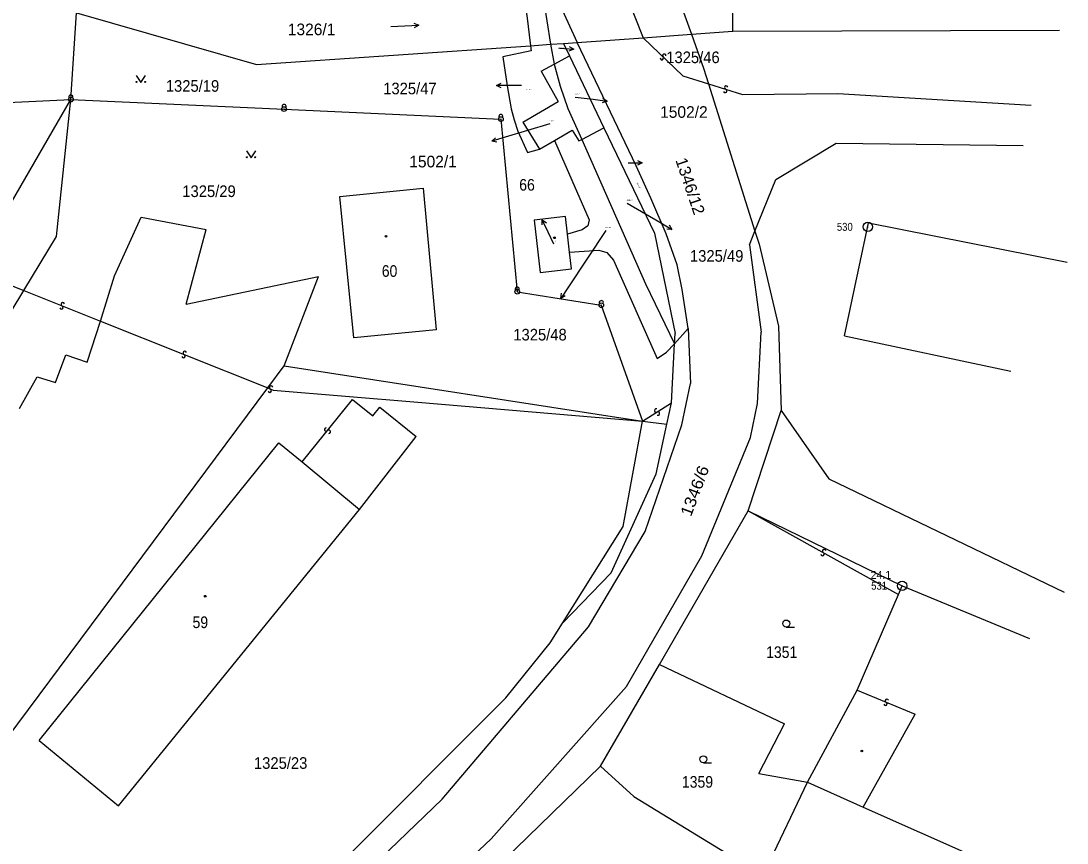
# Model space of a CAD drawing. Extents: x -871901 to -870967, y -1075952 to -1074892.
# Drawn here: x -871136.9 to -871047, y -1075290 to -1075219.4 of the extents above; entities that cross this region are included whole.
import ezdxf
from ezdxf.enums import TextEntityAlignment as Align

# ---------------------------------------------------------------- set-up
doc = ezdxf.new("R2010")
doc.units = 0
doc.header["$LTSCALE"] = 0.4
for name, color, linetype, lineweight in [('1', 7, 'Continuous', 25), ('16', 7, 'Continuous', 25), ('24', 7, 'Continuous', 25), ('25', 7, 'Continuous', 25), ('4', 7, 'Continuous', 25)]:
    doc.layers.add(name, color=color, linetype=linetype, lineweight=lineweight)
for name, color, linetype in [('17', 7, 'Continuous'), ('18', 7, 'Continuous'), ('19', 7, 'Continuous')]:
    doc.layers.add(name, color=color, linetype=linetype)

msp = doc.modelspace()

# ---------------------------------------------------------------- linework, layer by layer
at = {"layer": '1'}
for p, q in [((-871132.14, -1075218.66), (-871116.67, -1075223.11)), ((-871083.4, -1075220.8), (-871079.27, -1075220.49)), ((-871075.69, -1075220.23), (-871047.62, -1075220.14)), ((-871090.25, -1075221.28), (-871089.08, -1075221.2)), ((-871090.25, -1075221.28), (-871089.74, -1075222.36)), ((-871089.08, -1075221.2), (-871083.4, -1075220.8)), ((-871089.74, -1075222.36), (-871086.79, -1075228.53)), ((-871092.19, -1075223.66), (-871090.73, -1075226.28)), ((-871149.91, -1075255.96), (-871132.62, -1075226.11)), ((-871133.87, -1075237.87), (-871132.62, -1075226.11)), ((-871132.62, -1075226.11), (-871114.29, -1075226.93)), ((-871114.29, -1075226.93), (-871095.65, -1075227.79)), ((-871093.75, -1075228.06), (-871090.73, -1075226.28)), ((-871095.65, -1075227.79), (-871094.24, -1075242.63)), ((-871093.75, -1075228.06), (-871092.33, -1075230.38)), ((-871089.52, -1075228.73), (-871088.95, -1075229.67)), ((-871072.01, -1075232.97), (-871066.83, -1075229.86)), ((-871066.83, -1075229.86), (-871050.73, -1075230.05)), ((-871073.8, -1075237.43), (-871072.01, -1075232.97)), ((-871126.58, -1075236.21), (-871120.98, -1075237.29)), ((-871066.09, -1075246.41), (-871064.05, -1075236.72)), ((-871064.05, -1075236.72), (-871046.96, -1075240.09)), ((-871122.72, -1075243.71), (-871120.98, -1075237.29)), ((-871136.68, -1075242.53), (-871133.87, -1075237.87)), ((-871122.72, -1075243.71), (-871111.33, -1075241.33)), ((-871141.5, -1075250.52), (-871136.68, -1075242.53)), ((-871094.24, -1075242.63), (-871087.01, -1075243.79)), ((-871087.01, -1075243.79), (-871083.47, -1075253.75)), ((-871066.09, -1075246.41), (-871051.8, -1075249.47)), ((-871133.96, -1075250.43), (-871133.07, -1075248.06)), ((-871133.07, -1075248.06), (-871131.22, -1075248.69)), ((-871114.29, -1075249), (-871083.47, -1075253.75)), ((-871137.04, -1075252.66), (-871135.52, -1075249.95)), ((-871135.52, -1075249.95), (-871133.96, -1075250.43)), ((-871156.43, -1075305.59), (-871115.7, -1075250.9)), ((-871081.37, -1075254), (-871080.98, -1075252.18)), ((-871074.38, -1075261.46), (-871071.55, -1075252.85)), ((-871083.47, -1075253.75), (-871081.37, -1075254)), ((-871082.28, -1075258.28), (-871081.37, -1075254)), ((-871135.35, -1075281.2), (-871114.73, -1075255.63)), ((-871114.73, -1075255.63), (-871112.73, -1075257.25)), ((-871112.73, -1075257.25), (-871107.81, -1075261.35)), ((-871086.17, -1075266.8), (-871082.28, -1075258.28)), ((-871067.46, -1075258.72), (-871047.21, -1075268.46)), ((-871128.52, -1075286.81), (-871107.81, -1075261.35)), ((-871082.01, -1075274.66), (-871074.38, -1075261.46)), ((-871074.38, -1075261.46), (-871061.14, -1075267.9)), ((-871090.35, -1075271.13), (-871086.17, -1075266.8)), ((-871065.01, -1075276.88), (-871061.46, -1075268.64)), ((-871091.41, -1075272.82), (-871090.35, -1075271.13)), ((-871095.22, -1075277.55), (-871091.41, -1075272.82)), ((-871087.07, -1075283.41), (-871082.01, -1075274.66)), ((-871082.01, -1075274.66), (-871071.25, -1075279.76)), ((-871069.29, -1075284.78), (-871065.01, -1075276.88)), ((-871109.75, -1075292.07), (-871095.22, -1075277.55)), ((-871073.47, -1075284.05), (-871071.25, -1075279.76)), ((-871135.35, -1075281.2), (-871128.52, -1075286.81)), ((-871095.43, -1075291.53), (-871087.07, -1075283.41)), ((-871087.07, -1075283.41), (-871084.21, -1075286.02)), ((-871073.47, -1075284.05), (-871069.29, -1075284.78)), ((-871073.1, -1075292.79), (-871069.29, -1075284.78)), ((-871069.29, -1075284.78), (-871064.49, -1075286.92)), ((-871084.21, -1075286.02), (-871073.1, -1075292.79)), ((-871064.49, -1075286.92), (-871054.81, -1075291.23))]:
    msp.add_line(p, q, dxfattribs=at)
for points in [[(-871132.62, -1075226.11), (-871132.14, -1075218.66), (-871123.91, -1075214.69)], [(-871079.27, -1075220.49), (-871075.69, -1075220.23), (-871075.68, -1075215.86)], [(-871079.27, -1075220.49), (-871078.22, -1075223.41), (-871077.79, -1075224.77), (-871073.8, -1075237.43)], [(-871116.67, -1075223.11), (-871093.1, -1075221.48), (-871091.39, -1075221.36), (-871090.25, -1075221.28)], [(-871093.1, -1075221.48), (-871093.05, -1075221.91), (-871095.49, -1075222.43), (-871095.12, -1075224.94), (-871094.75, -1075226.9), (-871094.5, -1075227.84), (-871094.19, -1075228.83), (-871093.36, -1075230.65), (-871092.33, -1075230.38)], [(-871091.39, -1075221.36), (-871091.06, -1075223.06), (-871090.54, -1075224.97), (-871089.88, -1075226.87), (-871088.7, -1075229.54), (-871083.2, -1075241.94), (-871080.72, -1075247.11)], [(-871089.74, -1075239.24), (-871087.22, -1075239.05), (-871086.55, -1075239.25), (-871085.96, -1075239.92), (-871082.22, -1075248.38), (-871081.4, -1075247.82), (-871080.72, -1075247.11), (-871079.54, -1075245.79), (-871080.05, -1075242.43), (-871080.49, -1075240.33), (-871081.43, -1075237.66), (-871082.74, -1075234.58), (-871084.01, -1075231.8), (-871089.08, -1075221.2)], [(-871092.19, -1075223.66), (-871091.06, -1075223.06), (-871089.74, -1075222.36)], [(-871142.34, -1075235.78), (-871141.97, -1075234.83), (-871140.11, -1075230.1), (-871138.66, -1075226.39), (-871132.62, -1075226.11)], [(-871092.33, -1075230.38), (-871091.05, -1075229.63), (-871089.52, -1075228.73)], [(-871088.95, -1075229.67), (-871088.7, -1075229.54), (-871086.79, -1075228.53)], [(-871086.79, -1075228.53), (-871082.45, -1075237.6), (-871080.67, -1075246.21)], [(-871091.05, -1075229.63), (-871088.06, -1075236.44), (-871088.18, -1075236.96), (-871088.65, -1075237.32), (-871089.92, -1075237.67), (-871090.09, -1075236.16), (-871092.79, -1075236.48), (-871092.27, -1075240.99), (-871089.57, -1075240.67), (-871089.74, -1075239.24), (-871089.92, -1075237.67)], [(-871131.22, -1075248.69), (-871130.08, -1075245.17), (-871128.88, -1075241.26), (-871126.58, -1075236.21)], [(-871073.8, -1075237.43), (-871073.45, -1075238.54), (-871071.78, -1075245.58)], [(-871115.7, -1075250.9), (-871114.29, -1075249), (-871111.33, -1075241.33)], [(-871071.78, -1075245.58), (-871071.55, -1075252.85), (-871067.46, -1075258.72)], [(-871080.98, -1075252.18), (-871080.72, -1075247.11), (-871080.67, -1075246.21)], [(-871061.46, -1075268.64), (-871061.14, -1075267.9), (-871050.19, -1075272.43)]]:
    msp.add_lwpolyline(points, dxfattribs=at)
msp.add_lwpolyline([(-871109.5, -1075234.44), (-871102.34, -1075233.74), (-871101.2, -1075245.89), (-871108.3, -1075246.6)], close=True, dxfattribs=at)
at = {"layer": '16'}
for p, q in [((-871090.62, -1075221.7), (-871090.58, -1075221.7)), ((-871090.58, -1075221.7), (-871089.381, -1075221.768)), ((-871094.83, -1075224.91), (-871096.03, -1075224.91)), ((-871093.88, -1075224.91), (-871094.83, -1075224.91)), ((-871089.26, -1075225.9), (-871087.7, -1075226.09)), ((-871087.7, -1075226.09), (-871086.509, -1075226.238)), ((-871091.45, -1075228.19), (-871095.29, -1075229.35)), ((-871095.29, -1075229.35), (-871096.438, -1075229.696)), ((-871084.69, -1075231.54), (-871083.49, -1075231.544)), ((-871084.78, -1075235.02), (-871081.97, -1075236.66)), ((-871091.57, -1075237.52), (-871092.086, -1075236.437)), ((-871081.97, -1075236.66), (-871080.936, -1075237.268)), ((-871091.09, -1075238.53), (-871091.57, -1075237.52)), ((-871086.61, -1075237.36), (-871089.83, -1075242.2)), ((-871089.83, -1075242.2), (-871090.495, -1075243.198))]:
    msp.add_line(p, q, dxfattribs=at)
for points in [[(-871089.769, -1075221.546), (-871089.381, -1075221.768), (-871089.793, -1075221.945)], [(-871095.63, -1075225.109), (-871096.03, -1075224.91), (-871095.63, -1075224.709)], [(-871086.881, -1075225.99), (-871086.509, -1075226.238), (-871086.931, -1075226.387)], [(-871095.998, -1075229.772), (-871096.438, -1075229.696), (-871096.113, -1075229.389)], [(-871083.889, -1075231.342), (-871083.49, -1075231.544), (-871083.89, -1075231.742)], [(-871092.094, -1075236.884), (-871092.086, -1075236.437), (-871091.733, -1075236.711)], [(-871081.179, -1075236.893), (-871080.936, -1075237.268), (-871081.382, -1075237.238)], [(-871090.107, -1075242.976), (-871090.495, -1075243.198), (-871090.44, -1075242.754)]]:
    msp.add_lwpolyline(points, dxfattribs=at)
at = {"layer": '24'}
for centre, radius in [((-871132.6195, -1075226.1095), 0.2005), ((-871132.6195, -1075226.1095), 0.00851), ((-871114.2895, -1075226.9295), 0.2005), ((-871114.2895, -1075226.9295), 0.00851), ((-871095.6495, -1075227.7895), 0.2005), ((-871095.6495, -1075227.7895), 0.00851), ((-871064.0895, -1075237.0495), 0.4005), ((-871064.0895, -1075237.0495), 0.0125), ((-871094.2395, -1075242.6295), 0.2005), ((-871094.2395, -1075242.6295), 0.00851), ((-871087.0095, -1075243.7895), 0.2005), ((-871087.0095, -1075243.7895), 0.00851), ((-871061.1395, -1075267.8995), 0.4005), ((-871061.1395, -1075267.8995), 0.0125)]:
    msp.add_circle(centre, radius, dxfattribs=at)
for centre in [(-871132.6198, -1075225.8836), (-871114.2898, -1075226.7036), (-871095.6498, -1075227.5636), (-871094.2398, -1075242.4036), (-871087.0098, -1075243.5636)]:
    msp.add_arc(centre, 0.1746, 328.19485, 209.95045, dxfattribs=at)
at = {"layer": '25'}
for p, q in [((-871105.108, -1075219.836), (-871102.711, -1075219.723)), ((-871071.11, -1075271.45), (-871070.409, -1075271.45)), ((-871078.23, -1075283.12), (-871077.529, -1075283.12))]:
    msp.add_line(p, q, dxfattribs=at)
for points in [[(-871103.12, -1075219.542), (-871102.711, -1075219.723), (-871103.101, -1075219.942)], [(-871127.01, -1075224.029), (-871126.61, -1075224.63), (-871126.209, -1075224.029)], [(-871117.53, -1075230.509), (-871117.13, -1075231.11), (-871116.729, -1075230.509)]]:
    msp.add_lwpolyline(points, dxfattribs=at)
for centre, radius in [((-871126.97, -1075224.59), 0.04), ((-871126.249, -1075224.59), 0.04), ((-871117.49, -1075231.07), 0.04), ((-871116.769, -1075231.07), 0.04), ((-871105.5295, -1075237.8595), 0.0705), ((-871091.0395, -1075237.9895), 0.0705), ((-871121.0695, -1075268.7995), 0.0705), ((-871071.1095, -1075271.1495), 0.3005), ((-871078.2295, -1075282.8195), 0.3005), ((-871064.6095, -1075282.0995), 0.0705)]:
    msp.add_circle(centre, radius, dxfattribs=at)
for centre, radius, start, end in [((-871081.8036, -1075222.5451), 0.1475, 172.97298, 45.50679), ((-871081.5964, -1075222.3351), 0.1474, 353.52624, 225.27593), ((-871076.2753, -1075225.0896), 0.1473, 19.80867, 252.18312), ((-871076.3648, -1075225.37), 0.147, 199.918, 72.20641), ((-871133.436, -1075243.9861), 0.1472, 195.35905, 67.62325), ((-871133.3239, -1075243.7138), 0.1473, 15.541, 247.62183), ((-871122.9462, -1075248.1662), 0.1473, 195.73356, 67.62328), ((-871122.8342, -1075247.8934), 0.1475, 15.4214, 247.76923), ((-871115.5152, -1075251.1364), 0.1472, 195.73356, 67.98441), ((-871115.4049, -1075250.8632), 0.1475, 16.02831, 248.12849), ((-871082.2975, -1075252.8449), 0.1472, 69.8181, 301.63547), ((-871082.1421, -1075253.0956), 0.1478, 249.35499, 121.83186), ((-871110.6731, -1075254.476), 0.1471, 88.38454, 320.24689), ((-871110.4454, -1075254.6633), 0.1478, 268.0672, 141.04167), ((-871067.847, -1075264.9219), 0.1475, 7.85388, 240.30526), ((-871067.9921, -1075265.1784), 0.1473, 188.18653, 60.64559), ((-871062.5775, -1075278.0557), 0.1473, 194.50819, 66.73794), ((-871062.4622, -1075277.7847), 0.1471, 14.29327, 246.75217)]:
    msp.add_arc(centre, radius, start, end, dxfattribs=at)
at = {"layer": '4'}
for p, q in [((-871080.85, -1075216.08), (-871079.27, -1075220.49)), ((-871092.1, -1075216.66), (-871091.39, -1075221.36)), ((-871091.2, -1075216.61), (-871089.08, -1075221.2)), ((-871085.21, -1075216.27), (-871083.4, -1075220.8)), ((-871083.4, -1075220.8), (-871080.01, -1075224.08)), ((-871080.01, -1075224.08), (-871077.79, -1075224.77)), ((-871066.66, -1075225.6), (-871050.04, -1075226.59)), ((-871074.27, -1075238.6), (-871073.8, -1075237.43)), ((-871074.27, -1075238.6), (-871073.26, -1075246.1)), ((-871130.08, -1075245.17), (-871115.7, -1075250.9)), ((-871079.54, -1075245.79), (-871079.34, -1075250.53)), ((-871080.08, -1075254.08), (-871079.34, -1075250.53)), ((-871112.73, -1075257.25), (-871108.4, -1075251.89)), ((-871108.4, -1075251.89), (-871106.66, -1075253.29)), ((-871102.8, -1075252.13), (-871083.47, -1075253.75)), ((-871083.47, -1075253.75), (-871080.98, -1075252.18)), ((-871085.12, -1075262.8), (-871083.47, -1075253.75)), ((-871083.24, -1075263.25), (-871080.08, -1075254.08)), ((-871107.81, -1075261.35), (-871102.92, -1075255.07)), ((-871078.36, -1075265.32), (-871074.18, -1075255.16)), ((-871074.38, -1075261.46), (-871061.46, -1075268.64)), ((-871090.35, -1075271.13), (-871085.12, -1075262.8)), ((-871088.11, -1075271.44), (-871083.24, -1075263.25)), ((-871084.85, -1075276.56), (-871078.36, -1075265.32)), ((-871100.71, -1075286.26), (-871088.11, -1075271.44)), ((-871096.49, -1075289.67), (-871084.85, -1075276.56)), ((-871065.01, -1075276.88), (-871060.03, -1075278.95)), ((-871064.49, -1075286.92), (-871060.03, -1075278.95)), ((-871118.65, -1075303.5), (-871100.71, -1075286.26)), ((-871115.21, -1075307.2), (-871096.49, -1075289.67))]:
    msp.add_line(p, q, dxfattribs=at)
for points in [[(-871093.8, -1075216.76), (-871093.43, -1075218.88), (-871093.1, -1075221.48)], [(-871077.79, -1075224.77), (-871074.86, -1075225.68), (-871066.66, -1075225.6)], [(-871139.3, -1075241.49), (-871136.68, -1075242.53), (-871130.08, -1075245.17)], [(-871074.18, -1075255.16), (-871073.59, -1075252.24), (-871073.26, -1075246.1)], [(-871115.7, -1075250.9), (-871115.22, -1075251.09), (-871102.8, -1075252.13)], [(-871106.66, -1075253.29), (-871106.05, -1075252.54), (-871102.92, -1075255.07)]]:
    msp.add_lwpolyline(points, dxfattribs=at)

# ---------------------------------------------------------------- texts
at = {"layer": '16'}
for s, width, p in [('1325/46', 0.95, (-871079.13, -1075222.98)), ('1325/47', 0.95, (-871103.47, -1075225.66)), ('66', 0.9, (-871093.3995, -1075233.94)), ('1325/49', 0.95, (-871077.09, -1075240.05)), ('1325/48', 0.95, (-871092.28, -1075246.82))]:
    msp.add_text(s, height=1, dxfattribs=dict(at, width=width)).set_placement(p, align=Align.CENTER)
for s, p in [('1502/2', (-871079.9095, -1075227.68)), ('1502/1', (-871101.4795, -1075231.94))]:
    msp.add_text(s, height=1, dxfattribs=at).set_placement(p, align=Align.CENTER)
at = {"layer": '16', "width": 1.05}
msp.add_text('1346/12', height=1, rotation=288.702, dxfattribs=at).set_placement((-871079.8358, -1075233.7132), align=Align.CENTER)
at = {"layer": '17', "width": 0.9}
for s, p in [('530', (-871065.39, -1075237.39)), ('531', (-871062.44, -1075268.24))]:
    msp.add_text(s, height=0.68, dxfattribs=at).set_placement(p, align=Align.RIGHT)
at = {"layer": '17'}
msp.add_text('24.1', height=0.68, dxfattribs=at).set_placement((-871062.08, -1075267.31), align=Align.RIGHT)
at = {"layer": '18'}
msp.add_text('1326/1', height=1, dxfattribs=at).set_placement((-871113.97, -1075220.58))
at = {"layer": '18', "width": 0.95}
for s, p in [('1325/46', (-871090.49, -1075221.76)), ('1325/47', (-871093.23, -1075225.29)), ('1325/49', (-871084.58, -1075234.82)), ('1325/48', (-871086.41, -1075237.16))]:
    msp.add_text(s, height=0.1, dxfattribs=at).set_placement(p, align=Align.CENTER)
at = {"layer": '18'}
for s, width, p in [('1325/19', 0.95, (-871124.46, -1075225.44)), ('1325/29', 0.95, (-871123.04, -1075234.49)), ('1351', 0.9, (-871072.84, -1075274.11)), ('1325/23', 0.95, (-871116.88, -1075283.64)), ('1359', 0.9, (-871080.08, -1075285.26))]:
    msp.add_text(s, height=1, dxfattribs=dict(at, width=width)).set_placement(p)
for s, p in [('1502/2', (-871089.0595, -1075225.7)), ('1502/1', (-871091.2495, -1075227.99))]:
    msp.add_text(s, height=0.1, dxfattribs=at).set_placement(p, align=Align.CENTER)
at = {"layer": '18', "width": 1.15}
msp.add_text('1346/12', height=0.1, rotation=297.202, dxfattribs=at).set_placement((-871083.8613, -1075233.4956), align=Align.CENTER)
at = {"layer": '18', "width": 1.1}
msp.add_text('1346/6', height=1, rotation=69.301, dxfattribs=at).set_placement((-871079.306, -1075262.023))
at = {"layer": '19', "width": 0.9}
for s, height, p in [('66', 0.1, (-871090.8895, -1075238.33)), ('60', 1, (-871105.2195, -1075241.35))]:
    msp.add_text(s, height=height, dxfattribs=at).set_placement(p, align=Align.CENTER)
msp.add_text('59', height=1, dxfattribs=at).set_placement((-871122.16, -1075271.54))

doc.saveas('drawing.dxf')
